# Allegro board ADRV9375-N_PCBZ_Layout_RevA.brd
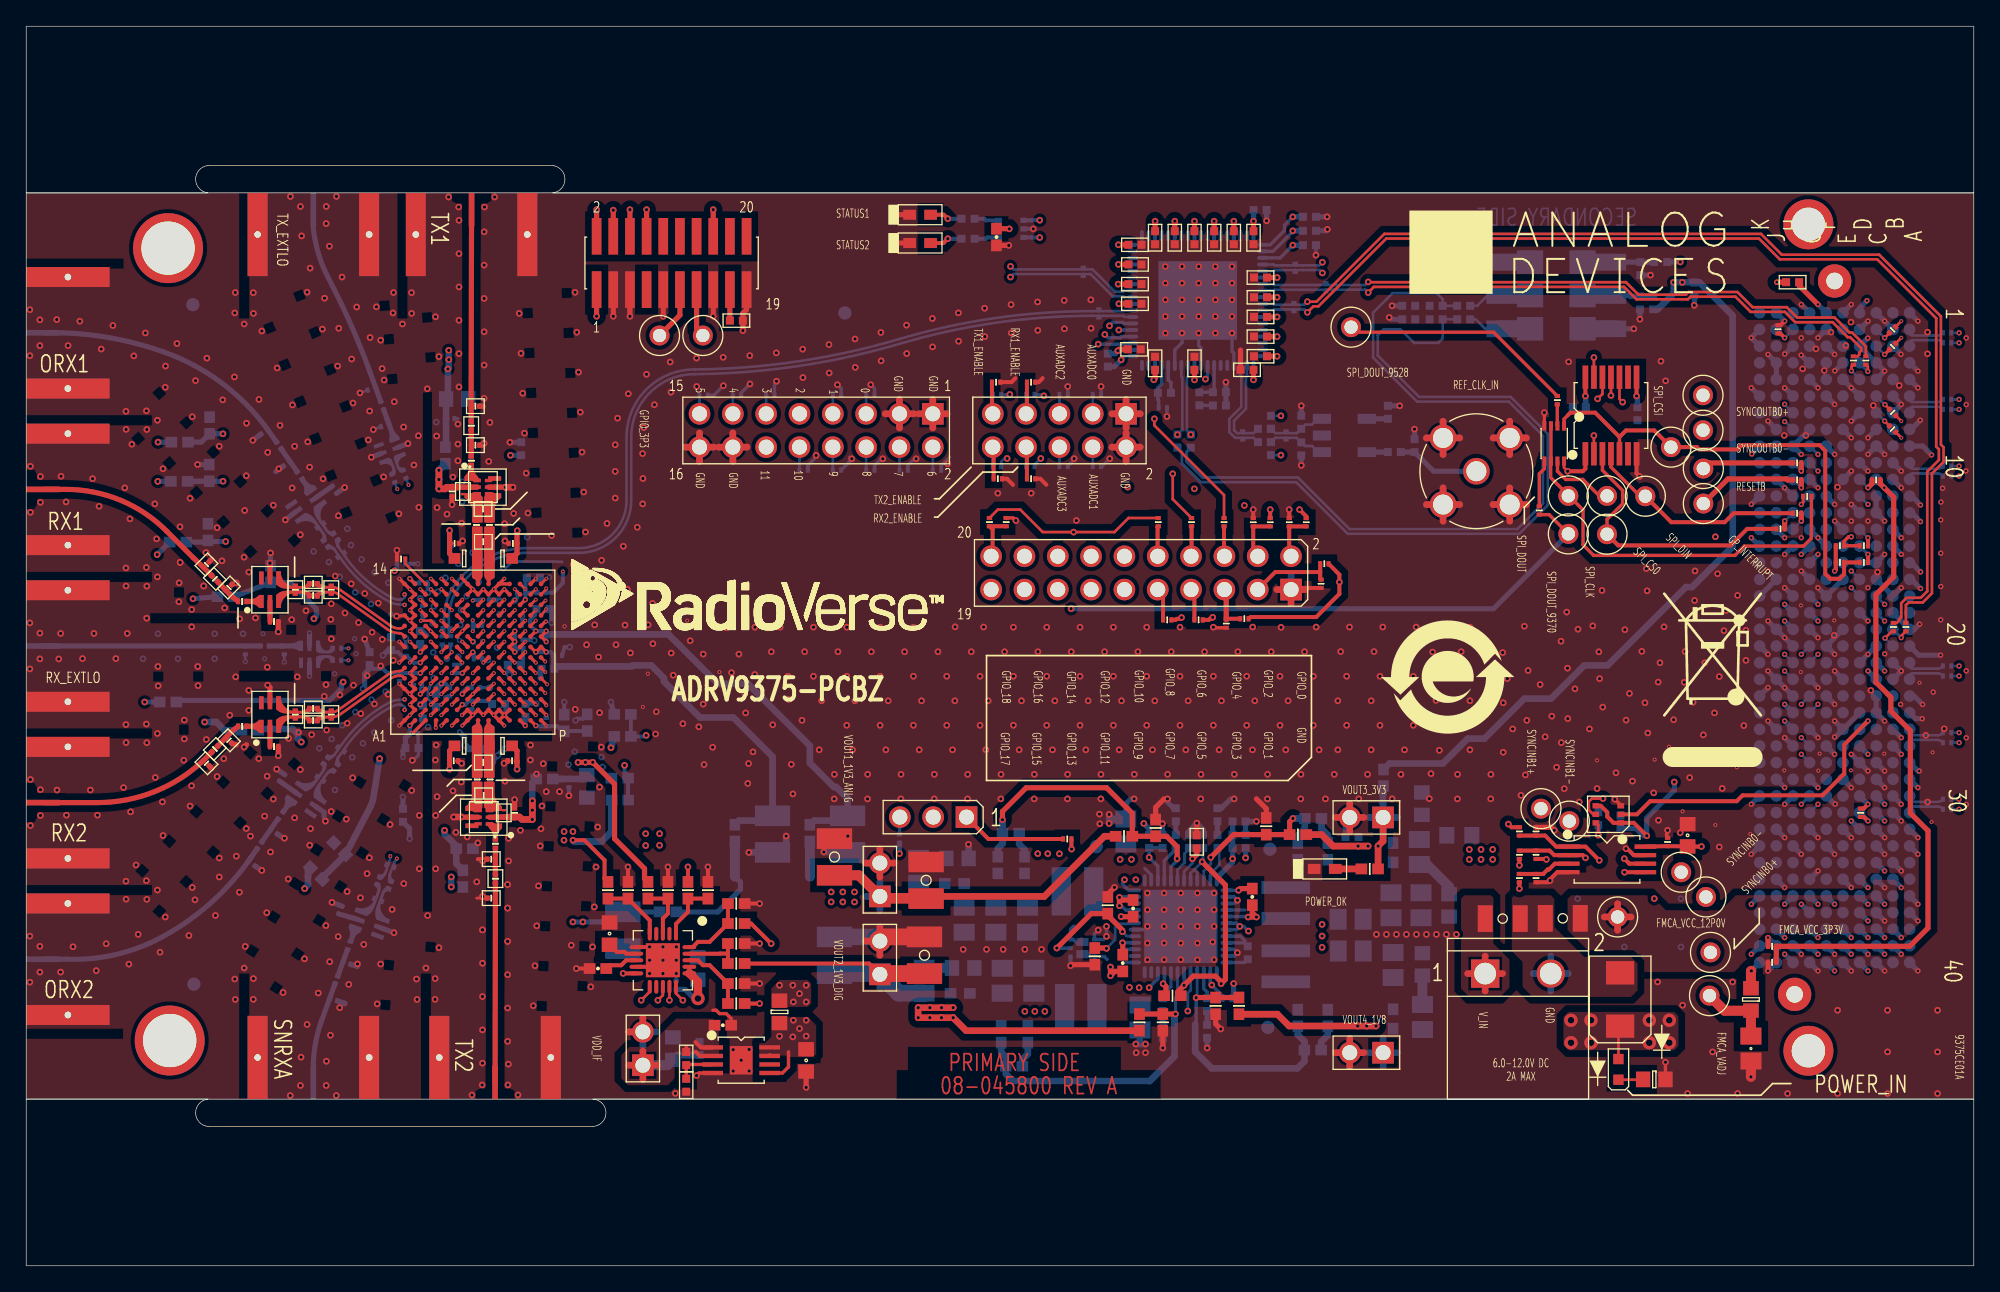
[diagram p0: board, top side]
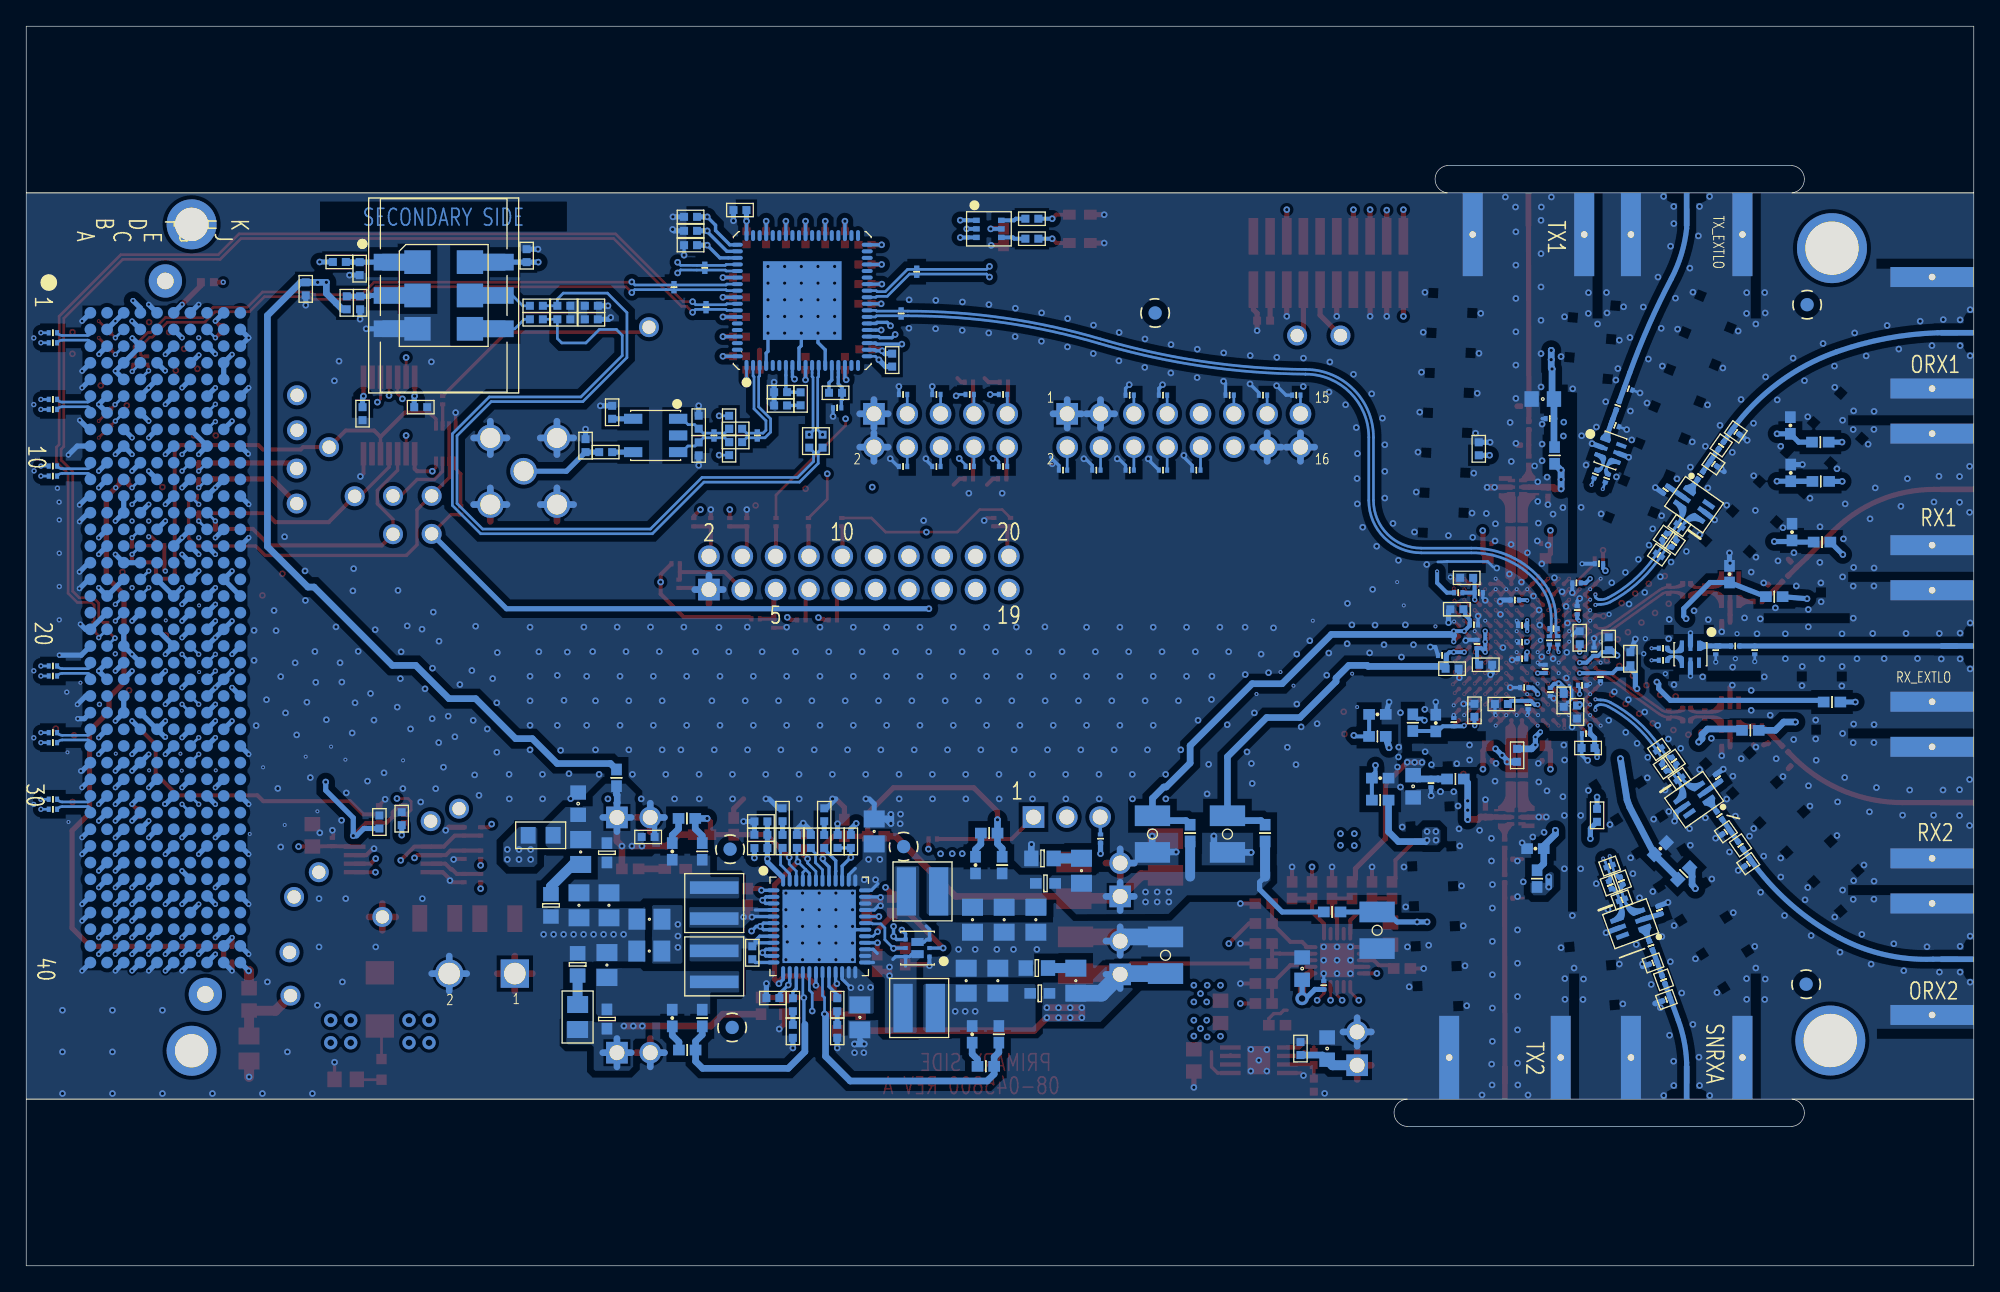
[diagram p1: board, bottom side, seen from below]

Outline 148.44 x 94.49 mm; copper layers: TOP, L2_GND, L3_PWR, L4_GND, L5_SIG, L6_GND, L7_SIG, L8_SIG, L9_GND, L10_SIG, L11_GND, L12_PWR, L13_GND, BOTTOM. Coordinates in mm from the lower left corner of the outline.
Outline path: 0,81.79 0,94.49 148.44,94.49 148.44,81.79 ; 0,81.79 0,12.7 ; 0,81.79 13.85,81.79 arc(12.91,82.83) 13.85,83.87 40.14,83.87 arc(41.06,82.83) 40.14,81.79 148.44,81.79 ; 0,81.79 148.44,81.79 ; 0,12.7 0,0 148.44,0 148.44,12.7 ; 0,12.7 148.44,12.7 ; 0,12.7 13.85,12.7 arc(12.91,11.66) 13.85,10.62 43.19,10.62 arc(44.19,11.66) 43.19,12.7 148.44,12.7 ; 148.44,12.7 148.44,81.79

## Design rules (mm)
net group DIFFPAIR0: nets SERDOUT0+ SERDOUT0-
net group DIFFPAIR1: nets SERDOUT1+ SERDOUT1-
net group DIFFPAIR2: nets SERDOUT3+ SERDOUT3-
net group DIFFPAIR3: nets SERDIN3+ SERDIN3-
net group DIFFPAIR4: nets SERDIN0+ SERDIN0-
net group DIFFPAIR5: nets SERDIN2+ SERDIN2-
net group DIFFPAIR13: nets SERDOUT2+ SERDOUT2-
net group DIFFPAIR15: nets SERDIN1+ SERDIN1-
net group DIFFPAIR16: nets TX_EXTLO+ TX_EXTLO-
net group DIFFPAIR17: nets ORX1+ ORX1-
net group DIFFPAIR18: nets RX1+ RX1-
net group DIFFPAIR19: nets RX2+ RX2-
net group DIFFPAIR20: nets ORX2+ ORX2-
net group DIFFPAIR22: nets RX_EXTLO+ RX_EXTLO-
net group DIFFPAIR24: nets DEV_CLK_IN+ DEV_CLK_IN-
net group DIFFPAIR26: nets GPIO_16 GPIO_17
net group DIFFPAIR27: nets GPIO_13 GPIO_14
net group DIFFPAIR28: nets GPIO_11 GPIO_12
net group DIFFPAIR29: nets GPIO_9 GPIO_10
net group DIFFPAIR30: nets GPIO_8 GPIO_15
net group DIFFPAIR36: nets SYNCOUTB0+ SYNCOUTB0-
net group DIFFPAIR37: nets SYNCINB0+ SYNCINB0-
net group DIFFPAIR38: nets SYNCINB1+ SYNCINB1-
net group DIFFPAIR56: nets SYSREF_IN+ SYSREF_IN-
net group DIFFPAIR59: nets CLK+ CLK-
net group DIFFPAIR61: nets UNNAMED_9_CAP_I337_N1 UNNAMED_9_CAP_I338_N1
net group DIFFPAIR62: nets SNRXA+ SNRXA-
net group DIFFPAIR63: nets FPGA_SYSREF+ FPGA_SYSREF-
net group DIFFPAIR64: nets UNNAMED_6_AD9370V2_I832_SERDI_3 UNNAMED_6_AD9370V2_I832_SERDIN2
net group DIFFPAIR65: nets UNNAMED_6_AD9370V2_I832_SERDI_1 UNNAMED_6_AD9370V2_I832_SERDIN0
net group DIFFPAIR66: nets UNNAMED_6_AD9370V2_I832_SERDI_4 UNNAMED_6_AD9370V2_I832_SERDIN3
net group DIFFPAIR67: nets UNNAMED_6_AD9370V2_I832_SERDI_2 UNNAMED_6_AD9370V2_I832_SERDIN1
net group DIFFPAIR68: nets UNNAMED_6_AD9370V2_I832_SERDO_1 UNNAMED_6_AD9370V2_I832_SERDOUT
net group DIFFPAIR69: nets UNNAMED_6_AD9370V2_I832_SERDO_4 UNNAMED_6_AD9370V2_I832_SERDO_5
net group DIFFPAIR70: nets UNNAMED_6_AD9370V2_I832_SERDO_2 UNNAMED_6_AD9370V2_I832_SERDO_3
net group DIFFPAIR71: nets UNNAMED_6_AD9370V2_I832_SERDO_6 UNNAMED_6_AD9370V2_I832_SERDO_7
net group DIFFPAIR72: nets VCXO_IN+ VCXO_IN-
net group DIFFPAIR73: nets UNNAMED_5_CAP_I916_N1 UNNAMED_5_RES_I897_N2
net group DIFFPAIR74: nets FPGA_REF_CLK+ FPGA_REF_CLK-
net group DIFFPAIR75: nets DIR_CLK+ DIR_CLK-
net group DIFFPAIR76: nets FPGA_AUX_CLK+ FPGA_AUX_CLK-
nets with their own width: min track width 0.254; nets AGND

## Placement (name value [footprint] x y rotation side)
C200  TBD0201  [C0201]  13.74 53.45 45 top
C201  18pF  [C0201]  14.37 52.37 315 top
C202  TBD0201  [C0201]  15.45 51.7 45 top
C203  TBD0201  [C0201]  18.89 49.1 0 top
C204  TBD0201  [C0201]  20.51 51.54 90 top
C205  18pF  [C0201]  21.88 51.08 0 top
C206  18pF  [C0201]  21.88 51.99 0 top
C207  TBD0201  [C0201]  23.25 51.54 90 top
C208  TBD0201  [C0201]  13.74 38.31 315 top
C209  18pF  [C0201]  14.37 39.39 45 top
C211  TBD0201  [C0201]  15.45 40.06 315 top
C212  TBD0201  [C0201]  18.89 39.58 0 top
C213  TBD0201  [C0201]  20.51 42.02 90 top
C214  18pF  [C0201]  21.88 41.56 0 top
C215  18pF  [C0201]  21.88 42.48 0 top
C216  TBD0201  [C0201]  23.25 42.02 90 top
C217  TBD0201  [C0201]  23.43 20.29 340 bottom
C218  18pF  [C0201]  23.64 21.8 70 bottom
C219  TBD0201  [C0201]  24.45 23.08 340 bottom
C220  TBD0201  [C0201]  23.95 27.12 70 bottom
C221  TBD0201  [C0201]  26.82 27.89 160 bottom
C222  18pF  [C0201]  27.71 29.02 70 bottom
C223  18pF  [C0201]  26.85 29.34 70 bottom
C224  TBD0201  [C0201]  27.75 30.47 160 bottom
C225  TBD0201  [C0201]  18.14 63.57 215 bottom
C226  18pF  [C0201]  19.25 62.53 305 bottom
C227  TBD0201  [C0201]  19.84 61.13 215 bottom
C228  TBD0201  [C0201]  23.49 59.16 305 bottom
C229  TBD0201  [C0201]  22.42 56.44 215 bottom
C230  18pF  [C0201]  23.58 55.57 305 bottom
C231  18pF  [C0201]  22.83 55.05 305 bottom
C232  TBD0201  [C0201]  23.99 54.19 215 bottom
C233  TBD0201  [C0201]  17.19 30.65 325 bottom
C234  18pF  [C0201]  17.78 32.05 55 bottom
C235  TBD0201  [C0201]  18.89 33.09 325 bottom
C236  18pF  [C0201]  19.5 37.19 235 bottom
C237  TBD0201  [C0201]  22.42 37.12 325 bottom
C238  18pF  [C0201]  22.83 38.5 55 bottom
C239  18pF  [C0201]  23.58 37.98 55 bottom
C240  TBD0201  [C0201]  23.99 39.36 325 bottom
C241  18pF  [C0201]  16.47 41.12 0 top
C242  18pF  [C0201]  24.6 24.41 70 bottom
C243  18pF  [C0201]  20.84 60.24 305 bottom
C244  18pF  [C0201]  19.38 34.33 55 bottom
C245  18pF  [C0201]  16.47 50.64 0 top
C301  18pF  [C0201]  33.92 64.04 90 top
C302  18pF  [C0201]  35.76 29.51 270 top
C303  TBD0201  [C0201]  34.81 57.69 0 top
C304  TBD0201  [C0201]  34.86 35.86 180 top
C305  18pF  [C0201]  33.92 61.37 90 top
C306  18pF  [C0201]  35.76 32.18 270 top
C307  TBD0201  [C0201]  32.65 55.06 0 top
C308  TBD0201  [C0201]  37.09 55.06 180 top
C309  TBD0201  [C0201]  34.32 56.48 90 top
C310  TBD0201  [C0201]  35.3 56.48 90 top
C311  TBD0201  [C0201]  34.84 55.19 0 top
C315  TBD0201  [C0201]  37.03 38.49 180 top
C316  TBD0201  [C0201]  32.58 38.49 0 top
C317  TBD0201  [C0201]  35.35 37.07 270 top
C318  TBD0201  [C0201]  34.37 37.07 270 top
C319  TBD0201  [C0201]  34.84 38.36 180 top
C320  10UF  [C0603]  32.85 66.07 0 bottom
C321  0.1uF  [C0201]  32.32 64.58 0 bottom
C322  0.1uF  [C0201]  32.46 59.02 270 top
C323  TBD0201  [C0201]  34.23 62.56 0 top
C324  TBD0201  [C0201]  34.23 65.53 0 top
C325  10UF  [C0603]  42.73 36.55 270 bottom
C326  0.1uF  [C0201]  41.37 36.79 270 bottom
C327  0.1uF  [C0201]  37.22 34.53 90 top
C328  TBD0201  [C0201]  35.44 31 180 top
C329  TBD0201  [C0201]  35.44 28.03 180 top
C330  TBD0201  [C0201]  16.69 46.93 270 bottom
C331  TBD0201  [C0201]  19.67 46.93 270 bottom
C332  100pF  [C0201]  23.68 47.07 0 bottom
C333  100pF  [C0201]  23.68 46.15 0 bottom
C334  TBD0201  [C0201]  26.33 66.86 200 bottom
C335  TBD0201  [C0201]  27.34 64.07 200 bottom
C336  100pF  [C0201]  28.84 60.34 290 bottom
C337  100pF  [C0201]  27.98 60.03 290 bottom
C401  0.1UF  [C0402]  104.28 62.02 180 bottom
C402  0.1UF  [C0402]  94.37 63.8 180 bottom
C403  0.1UF  [C0402]  94.37 62.79 180 bottom
C404  0.33uF  [C0402]  123.02 76.01 270 bottom
C405  0.1UF  [C0402]  110.3 77 270 bottom
C406  0.1UF  [C0402]  105.37 73.18 0 bottom
C407  0.1UF  [C0402]  94.87 62.29 270 bottom
C408  0.1UF  [C0402]  88.76 62.86 90 bottom
C409  0.1UF  [C0402]  94.87 64.3 90 bottom
C410  180pF  [C0402]  90.94 66.59 180 bottom
C411  1uF  [C0402]  90.94 65.58 180 bottom
C412  1000pF  [C0402]  86.76 66.55 0 bottom
C413  0.47uF  [C0201]  86.63 65.4 0 bottom
C414  0.1UF  [C0402#2]  73.95 78.42 90 top
C415  0.1UF  [C0402]  121.52 33.83 270 bottom
C416  0.1UF  [C0402]  119.82 34.08 270 bottom
C417  0.1UF  [C0402]  122.81 64.96 90 bottom
C418  0.1UF  [C0402]  118.37 65.45 0 bottom
C419  0.1UF  [C0402#2]  53.1 18.33 180 top
C420  1uF  [C0402]  94.04 80.48 0 bottom
C421  0.1UF  [C0402]  84.51 77.83 180 top
C422  0.1UF  [C0402]  84.51 76.33 180 top
C423  0.1UF  [C0402]  84.51 74.83 180 top
C424  0.1UF  [C0402]  84.51 73.33 180 top
C425  0.1UF  [C0402]  84.45 69.86 180 top
C426  0.1UF  [C0402]  86.04 68.79 270 top
C427  0.1UF  [C0402]  89.04 68.79 270 top
C428  0.1UF  [C0402]  93.04 68.3 0 top
C429  0.1UF  [C0402]  94.08 69.33 0 top
C430  0.1UF  [C0402]  94.08 70.83 0 top
C431  0.1UF  [C0402]  94.08 72.33 0 top
C432  0.1UF  [C0402]  94.08 73.83 0 top
C433  0.1UF  [C0402]  94.08 75.33 0 top
C434  0.1UF  [C0402]  93.54 78.36 90 top
C435  0.1UF  [C0402]  92.04 78.36 90 top
C436  0.1UF  [C0402]  90.54 78.36 90 top
C437  0.1UF  [C0402]  89.04 78.36 90 top
C438  0.1UF  [C0402]  87.54 78.36 90 top
C439  0.1UF  [C0402]  86.04 78.36 90 top
C501  0.1uF  [C0201]  31.71 47.67 270 bottom
C502  0.1uF  [C0201]  32.34 47.67 270 bottom
C503  0.1uF  [C0201]  79.07 60.93 0 bottom
C504  0.1uF  [C0201]  79.07 66.42 0 bottom
C505  0.1uF  [C0201]  81.61 60.93 0 bottom
C506  0.1uF  [C0201]  81.61 66.42 0 bottom
C507  0.1uF  [C0201]  146.41 39.88 0 bottom
C508  0.1uF  [C0201]  146.41 40.64 0 bottom
C509  0.1uF  [C0201]  142.25 70.07 45 top
C510  0.1uF  [C0201]  142.25 71.34 45 top
C511  0.1uF  [C0201]  146.41 34.8 0 bottom
C512  0.1uF  [C0201]  146.41 35.56 0 bottom
C513  0.1uF  [C0201]  146.41 44.96 0 bottom
C514  0.1uF  [C0201]  146.41 45.72 0 bottom
C515  0.1uF  [C0201]  146.41 70.36 0 bottom
C516  0.1uF  [C0201]  146.41 71.12 0 bottom
C517  0.1uF  [C0201]  146.41 65.28 0 bottom
C518  0.1uF  [C0201]  146.41 66.04 0 bottom
C519  0.1uF  [C0201]  142.25 63.78 315 top
C520  0.1uF  [C0201]  142.25 65.05 315 top
C521  0.1uF  [C0201]  146.41 60.2 0 bottom
C522  0.1uF  [C0201]  146.41 60.96 0 bottom
C523  0.1uF  [C0201]  64.33 66.37 0 bottom
C524  0.1uF  [C0201]  61.79 66.37 0 bottom
C525  0.1uF  [C0201]  56.71 66.37 0 bottom
C526  0.1uF  [C0201]  54.17 66.37 0 bottom
C527  0.1uF  [C0201]  51.63 66.37 0 bottom
C528  0.1uF  [C0201]  69.41 60.65 0 bottom
C529  0.1uF  [C0201]  66.87 60.65 0 bottom
C530  0.1uF  [C0201]  64.33 60.65 0 bottom
C531  0.1uF  [C0201]  61.79 60.65 0 bottom
C532  0.1uF  [C0201]  59.25 60.65 0 bottom
C601  100UF  [C1210]  68.59 29.38 90 top
C602  100UF  [C1210]  61.6 31.16 90 top
C603  1uF  [C0402]  29.4 39.47 0 bottom
C604  1uF  [C0402]  31.25 43.1 270 bottom
C605  0.1uF  [C0201]  29.55 40.56 0 bottom
C606  0.1uF  [C0201]  32.27 43.73 270 bottom
C608  100UF  [C1210]  45.48 25.57 270 bottom
C609  1uF  [C0402]  36 42.82 0 bottom
C610  0.1uF  [C0201]  33.97 42.74 270 bottom
C611  100UF  [C1210]  56.88 32.91 270 bottom
C612  1uF  [C0402]  39.76 45.51 180 bottom
C613  0.1uF  [C0201]  40.52 46.53 0 bottom
C614  1uF  [C0402#2]  33.41 31.8 0 bottom
C615  0.1uF  [C0201]  34.26 44.07 0 bottom
C616  1uF  [C0402#2]  41 41.37 90 bottom
C617  0.1uF  [C0201]  39.63 41.44 90 bottom
C618  1uF  [C0402#2]  45.45 42.03 180 bottom
C619  0.1uF  [C0201]  32.66 45.5 90 bottom
C620  1uF  [C0402]  26.17 46.27 90 bottom
C621  0.1uF  [C0201]  28.46 44.88 270 bottom
C622  1uF  [C0402#2]  45.24 37.17 180 bottom
C623  0.1uF  [C0201]  34.43 47.54 0 bottom
C624  1uF  [C0402]  27.82 47.42 90 bottom
C625  0.1uF  [C0201]  28.94 46.81 90 bottom
C626  1uF  [C0402#2]  18.62 52.72 90 bottom
C627  0.1uF  [C0201]  34.43 46.27 0 bottom
C628  1uF  [C0402#2]  23.89 31.8 135 bottom
C629  0.1uF  [C0201]  29.85 44.24 180 bottom
C630  1uF  [C0402#2]  13.95 60.44 90 bottom
C631  0.1uF  [C0201]  34.43 48.81 0 bottom
C632  1uF  [C0402#2]  13.85 55.93 90 bottom
C633  0.1uF  [C0201]  28.56 53.51 0 bottom
C634  1uF  [C0402#2]  13.98 64.05 90 bottom
C635  0.1uF  [C0201]  34.98 50.75 0 bottom
C636  1uF  [C0402]  37.2 45.82 180 bottom
C637  0.1uF  [C0201]  37.86 47.4 90 bottom
C638  100UF  [C1210]  68.46 23.67 90 top
C639  100UF  [C1210]  61.6 23.67 90 bottom
C640  0.1uF  [C0201]  30.22 49.98 90 bottom
C641  0.1uF  [C0201]  30.28 52.05 0 bottom
C642  0.01UF  [C0201]  37.73 51.31 180 bottom
C643  1uF  [C0402]  38.65 52.44 0 bottom
C644  1uF  [C0402]  38.06 42.34 90 bottom
C645  1uF  [C0402]  30.03 47.88 90 bottom
C646  1uF  [C0402]  30.24 42.21 270 bottom
C647  1uF  [C0402]  37.73 62.28 90 bottom
C648  10UF  [C0603]  51.19 22.65 90 bottom
C649  0.1uF  [C0201]  49.54 21.38 90 bottom
C650  10UF  [C0603]  44.46 25.32 90 top
C651  1uF  [C0402#2]  43.58 22.66 180 top
C652  100UF  [C1210]  62.6 32.91 270 bottom
C653  1uF  [C0402]  39.4 50.05 0 bottom
C654  0.1uF  [C0201]  38.1 48.86 180 bottom
C701  10uF  [C0805H60]  83.81 33.11 90 bottom
C702  1uF  [C0402]  89.7 32.35 270 bottom
C703  1uF  [C0402]  89.22 32.32 270 top
C704  2700PF  [C0402]  87.62 34.38 270 bottom
C705  10uF  [C0805H60]  84.9 18.94 270 bottom
C706  2700PF  [C0402]  86.63 17.87 90 bottom
C707  10uF  [C0805H60]  100.94 26.42 0 bottom
C708  3300pF  [C0402]  90.79 34.38 270 bottom
C709  10uF  [C0805H60]  100.95 23.99 0 bottom
C710  3300pF  [C0402]  90 17.87 90 bottom
C711  TBD0402  [C0402]  91.53 20.41 180 bottom
C712  TBD0402  [C0402]  92.44 33.87 180 bottom
C713  0.1UF  [C0402#2]  84.37 27.24 90 top
C714  0.01UF  [C0402#2]  76.09 30.54 270 bottom
C715  0.1UF  [C0402#2]  83.58 23.08 90 top
C716  0.01UF  [C0402#2]  76.34 17.64 90 bottom
C717  0.1UF  [C0402#2]  93.45 28.12 270 top
C718  0.01UF  [C0402#2]  99.2 31.58 270 bottom
C719  0.1UF  [C0402]  93.1 23.86 90 bottom
C720  0.01UF  [C0402#2]  99.2 18.88 90 bottom
C721  47uF  [C0805H60]  76.31 26.38 270 bottom
C722  47uF  [C0805H60]  73.9 26.38 270 bottom
C723  47uF  [C0805H60]  71.49 26.38 270 bottom
C724  47uF  [C0805H60]  68.01 30.11 90 bottom
C725  47uF  [C0805H60]  76.8 21.73 90 bottom
C726  47uF  [C0805H60]  74.38 21.73 90 bottom
C727  47uF  [C0805H60]  68.44 21.73 90 bottom
C728  47uF  [C0805H60]  104.02 27.48 270 bottom
C729  47uF  [C0805H60]  106.18 31.54 270 bottom
C730  47uF  [C0805H60]  104.18 22.92 90 bottom
C731  22UF  [C0805H53]  106.41 18.96 90 bottom
C732  47uF  [C0805H60]  131.45 16.56 270 top
C733  4.7uF  [C0603]  59.45 15.66 90 top
C734  4.7uF  [C0603]  49.29 16.56 270 bottom
C735  0.01UF  [C0402]  51.32 16.56 270 bottom
C736  10UF  [C0603]  106.37 35.23 90 bottom
C737  0.01UF  [C0402]  101.04 32.69 0 bottom
C738  0.1UF  [C0402]  127.14 74.47 90 bottom
C739  47uF  [C0805H60]  106.31 27.48 270 bottom
C801  0.01UF  [C0201]  143.27 48.69 90 top
C802  0.01UF  [C0201]  142.31 48.69 90 top
C803  0.1uF  [C0201]  125.1 32.3 270 top
C804  10UF  [C0603]  126.63 32.81 90 top
C805  0.01UF  [C0201]  140.22 69.01 270 top
C806  0.01UF  [C0201]  139.26 69.01 270 top
CR701  S2A-TP  [DO214AA3]  121.48 20.3 90 top
D401  LNJ314G8TRA (green)  [LED0603]  68.13 77.96 0 top
D402  LNJ314G8TRA (green)  [LED0603]  68.13 80.12 0 top
DS701  LNJ912W8CRA1 (blue)  [LED0603-2]  121.36 14.97 90 top
DS702  LNJ314G8TRA (green)  [LED0603]  98.97 30.25 0 top
E601  30OHM  [L0402]  54.01 32.98 90 bottom
E602  30OHM  [L0402]  33.28 29.51 90 bottom
E603  30OHM  [L0402]  42.76 41.4 270 bottom
E604  47OHM AT 100MHZ  [L0402]  45.45 40.35 0 bottom
E605  30OHM  [L0402]  17.03 40.81 0 bottom
E606  47OHM AT 100MHZ  [L0402]  45.24 35.5 0 bottom
E607  30OHM  [L0402]  10.8 42.97 0 bottom
E608  47OHM AT 100MHZ  [L0402]  15.21 51 0 bottom
E609  30OHM  [L0402]  22.11 29.89 315 bottom
E610  30OHM  [L0402]  11.66 59.79 0 bottom
E611  47OHM AT 100MHZ  [L0402]  11.57 55.16 0 bottom
E612  30OHM  [L0402]  11.69 62.78 0 bottom
E613  30OHM  [L0402]  59.73 32.98 90 bottom
E701  120OHM  [L0603]  70.75 29.15 180 bottom
E702  470OHM  [L0603]  71.18 20.76 180 bottom
E703  470OHM  [L0603]  104.18 31.48 90 bottom
E704  470OHM  [L0603]  104.18 18.81 270 bottom
E705  39OHM  [L0805]  109.23 32.81 0 bottom
E706  30OHM  [L0402]  103.45 37.19 90 bottom
F701  2A  [F1206]  117.11 26.48 180 top
F702  2A  [F1206]  112.53 26.46 0 top
J200  132255-11  [CNAMPHENOL132255-11]  0.76 59.18 180 top
J201  132255-11  [CNAMPHENOL132255-11]  0.76 35.31 180 top
J202  132255-11  [CNAMPHENOL132255-11]  21.88 13.46 270 bottom
J203  132255-11  [CNAMPHENOL132255-11]  0.76 71.12 180 bottom
J204  132255-11  [CNAMPHENOL132255-11]  0.76 23.37 180 bottom
J305  132255-11  [CNAMPHENOL132255-11]  33.94 81.03 90 top
J306  132255-11  [CNAMPHENOL132255-11]  35.73 13.46 270 top
J307  132255-11  [CNAMPHENOL132255-11]  0.76 47.24 180 bottom
J308  132255-11  [CNAMPHENOL132255-11]  21.88 81.03 90 bottom
J401  142-0701-201  [CNJOHNSON142-0701-201]  110.53 60.57 0 top
L200  TBD0201  [L0201]  13.74 53.45 225 top
L201  TBD0201  [L0201]  14.37 52.37 135 top
L202  TBD0201  [L0201]  15.45 51.7 225 top
L204  TBD0201  [L0201]  20.51 51.54 90 top
L205  TBD0201  [L0201]  21.88 51.08 180 top
L206  TBD0201  [L0201]  21.88 51.99 180 top
L207  TBD0201  [L0201]  23.25 51.54 90 top
L208  TBD0201  [L0201]  13.74 38.31 135 top
L209  TBD0201  [L0201]  14.37 39.39 225 top
L211  TBD0201  [L0201]  15.45 40.06 135 top
L213  TBD0201  [L0201]  20.51 42.02 90 top
L214  TBD0201  [L0201]  21.88 41.56 180 top
L215  TBD0201  [L0201]  21.88 42.48 180 top
L216  TBD0201  [L0201]  23.25 42.02 90 top
L217  TBD0201  [L0201]  23.43 20.29 160 bottom
L218  TBD0201  [L0201]  23.64 21.8 250 bottom
L219  TBD0201  [L0201]  24.45 23.08 160 bottom
L221  TBD0201  [L0201]  26.82 27.89 160 bottom
L222  TBD0201  [L0201]  27.71 29.02 250 bottom
L223  TBD0201  [L0201]  26.85 29.34 250 bottom
L224  TBD0201  [L0201]  27.75 30.47 160 bottom
L225  TBD0201  [L0201]  18.14 63.57 35 bottom
L226  TBD0201  [L0201]  19.25 62.53 125 bottom
L227  TBD0201  [L0201]  19.84 61.13 35 bottom
L229  TBD0201  [L0201]  22.42 56.44 35 bottom
L230  TBD0201  [L0201]  23.58 55.57 125 bottom
L231  TBD0201  [L0201]  22.83 55.05 125 bottom
L232  TBD0201  [L0201]  23.99 54.19 35 bottom
L233  TBD0201  [L0201]  17.19 30.65 145 bottom
L234  TBD0201  [L0201]  17.78 32.05 235 bottom
L235  TBD0201  [L0201]  18.89 33.09 145 bottom
L237  TBD0201  [L0201]  22.42 37.12 145 bottom
L238  TBD0201  [L0201]  22.83 38.5 235 bottom
L239  TBD0201  [L0201]  23.58 37.98 235 bottom
L240  TBD0201  [L0201]  23.99 39.36 145 bottom
L301  TBD0201  [L0201]  33.92 64.04 270 top
L302  TBD0201  [L0201]  35.76 29.51 90 top
L303  TBD0201  [L0201]  34.81 57.69 180 top
L304  TBD0201  [L0201]  34.86 35.86 0 top
L305  TBD0201  [L0201]  33.28 59.02 270 top
L306  TBD0201  [L0201]  36.39 34.53 90 top
L307  TBD0603  [L0603]  33.38 53.92 180 top
L308  TBD0603  [L0603]  36.3 53.92 180 top
L311  TBD0201  [L0201]  34.84 55.19 180 top
L315  TBD0603  [L0603]  36.3 39.63 0 top
L316  TBD0603  [L0603]  33.38 39.63 0 top
L319  TBD0201  [L0201]  34.84 38.36 0 top
L323  TBD0201  [L0201]  34.23 62.56 180 top
L324  TBD0201  [L0201]  34.23 65.53 180 top
L328  TBD0201  [L0201]  35.44 31 0 top
L329  TBD0201  [L0201]  35.44 28.03 0 top
L340  27NH  [L0402]  31.95 61.77 270 bottom
L341  27NH  [L0402]  39.51 37.11 180 bottom
L700  2.2uH  [LSMSQ157H83]  80.12 28.54 180 bottom
L701  2.2uH  [LSMSQ157H83]  80.38 19.65 180 bottom
L702  6.8uH  [LSMSQ157H122]  96 27.65 90 bottom
L703  6.8uH  [LSMSQ157H122]  96 22.82 270 bottom
NOREF  -  [unnamed]  135.84 79.39 0 top
NOREF#2  -  [#2]  -140.27 -270.64 0 top
NOREF#3  -  [#2]  65.26 103.22 0 top
NOREF#4  -  [#2]  154.73 149.81 0 top
NOREF#5  -  [#2]  -96.05 -6.87 0 top
NOREF#6  -  [#2]  -140.27 -270.64 0 top
NOREF#7  -  [#2]  0 81.79 0 top
NOREF#8  -  [#2]  250.38 231.5 0 top
NOREF#9  -  [#2]  100.91 127.05 0 top
NOREF#10  -  [#2]  43.34 10.64 0 top
NOREF#11  -  [#2]  148.44 81.79 0 top
NOREF#12  -  [unnamed]  135.84 16.39 0 top
NOREF#13  -  [#2]  148.44 12.7 0 top
NOREF#14  -  [#2]  148.44 12.7 90 top
NOREF#15  -  [#2]  137.8 54.91 0 top
NOREF#16  -  [unnamed]  10.81 77.57 0 top
NOREF#17  -  [#2]  108.34 44.88 0 top
NOREF#18  -  [#2]  0 0 90 top
NOREF#19  -  [#2]  0 0 90 top
NOREF#20  -  [unnamed]  10.93 17.17 0 top
NOREF#21  -  [#2]  -140.27 -270.64 0 top
NOREF#22  -  [#2]  277 2.84 0 top
NOREF#23  -  [unnamed]  12.7 73.26 0 bottom
NOREF#24  -  [unnamed]  94.79 31.76 0 bottom
NOREF#25  -  [unnamed]  12.78 21.46 0 bottom
NOREF#26  -  [unnamed]  81.56 31.95 0 bottom
NOREF#27  -  [#2]  105.42 74.09 180 bottom
NOREF#28  -  [unnamed]  62.4 72.63 90 bottom
NOREF#29  -  [unnamed]  94.63 18.17 0 bottom
P501  TSW-105-08-G-D  [CNSAMTEC2X5H338LD36]  83.83 64.94 180 top
P502  PEC10DAAN  [CNBERGF2X10H335LD32]  96.4 51.55 180 top
P503  TSW-108-08-G-D-ST  [CNSAMTECTSW-108-08-G-D-ST]  69.1 64.94 180 top
P504  FTSH-110-01-L-DV-K  [CNHDR2X10H251]  49.19 76.44 0 top
P701  Z5.530.3225.0  [CNWIELAND3225]  111.2 22.27 0 top
P702  SAMTECTSW10608GS3PIN  [CNBERG1X3H205LD36]  71.67 34.2 180 top
P703  TSW-102-08-G-S  [CNSAMTEC1X2H330LD36]  65.06 28.16 90 top
P704  TSW-102-08-G-S  [CNSAMTEC1X2H330LD36]  65.06 22.21 90 top
P705  TSW-102-08-G-S  [CNSAMTEC1X2H330LD36]  103.42 34.18 180 top
P706  TSW-102-08-G-S  [CNSAMTEC1X2H330LD36]  103.42 16.24 180 top
P707  TSW-102-08-G-S  [CNSAMTEC1X2H330LD36]  47 15.29 90 top
P801  ASP-134488-01  [CNSAMTECASP-134488-01]  143.55 72.64 270 bottom
Q701  SIA906EDJ-T1-GE3  [POWERPAKSC70-6]  80.51 24.22 90 bottom
R201  0  [R0201]  14.37 52.37 315 top
R202  0  [R0201]  16.47 50.64 0 top
R203  0  [R0201]  18.89 49.1 0 top
R204  0  [R0201]  16.47 41.12 0 top
R205  0  [R0201]  21.88 51.08 0 top
R206  0  [R0201]  21.88 51.99 0 top
R207  0  [R0201]  24.6 24.41 70 bottom
R208  0  [R0201]  20.84 60.24 305 bottom
R209  0  [R0201]  14.37 39.39 45 top
R210  0  [R0201]  19.38 34.33 55 bottom
R212  0  [R0201]  18.89 39.58 0 top
R214  0  [R0201]  21.88 41.56 0 top
R215  0  [R0201]  21.88 42.48 0 top
R218  0  [R0201]  23.64 21.8 70 bottom
R220  0  [R0201]  23.95 27.12 70 bottom
R222  0  [R0201]  27.71 29.02 70 bottom
R223  0  [R0201]  26.85 29.34 70 bottom
R226  0  [R0201]  19.25 62.53 305 bottom
R228  0  [R0201]  23.49 59.16 305 bottom
R230  0  [R0201]  23.58 55.57 305 bottom
R231  0  [R0201]  22.83 55.05 305 bottom
R234  0  [R0201]  17.78 32.05 55 bottom
R236  0  [R0201]  19.5 37.19 55 bottom
R238  0  [R0201]  22.83 38.5 55 bottom
R239  0  [R0201]  23.58 37.98 55 bottom
R301  0  [R0201]  33.92 64.04 90 top
R302  0  [R0201]  35.76 29.51 270 top
R303  0  [R0201]  33.92 61.37 90 top
R304  0  [R0201]  35.76 32.18 270 top
R309  TBD0201  [R0201]  34.32 56.48 90 top
R310  TBD0201  [R0201]  35.3 56.48 90 top
R312  0  [R0201]  18.18 47.24 0 bottom
R313  0  [R0201]  27.13 65.57 290 bottom
R317  TBD0201  [R0201]  35.35 37.07 270 top
R318  TBD0201  [R0201]  34.37 37.07 270 top
R401  49.9  [R0402#2]  105.81 62.52 270 bottom
R402  0  [R0402#2]  103.78 65.06 270 bottom
R403  24.9  [R0402#2]  97.18 64.3 270 bottom
R404  24.9  [R0402#2]  97.18 62.27 270 bottom
R405  100  [R0201]  96.02 63.29 270 bottom
R406  100  [R0201]  92.72 63.29 270 bottom
R407  0  [R0402#2]  124.57 76.52 180 bottom
R408  0  [R0402#2]  124.01 73.41 270 bottom
R409  0  [R0402#2]  122.99 73.41 90 bottom
R410  0  [R0402#2]  109.56 72.15 180 bottom
R411  0  [R0402#2]  109.56 73.18 180 bottom
R412  49.9  [R0402#2]  107.46 72.15 0 bottom
R413  0  [R0402#2]  107.46 73.18 180 bottom
R414  0  [R0402#2]  87.74 62.86 90 bottom
R415  10.2K  [R0402#2]  89.42 66.09 90 bottom
R416  10K  [R0402#2]  82.44 69.04 270 bottom
R417  10K  [R0402#2]  97.8 77.8 180 bottom
R418  10K  [R0402#2]  97.8 79.96 0 bottom
R419  10K  [R0402#2]  97.8 78.89 0 bottom
R420  200  [R0402#2]  71.79 78.29 180 bottom
R421  200  [R0402#2]  71.79 79.82 180 bottom
R422  100  [R0201]  96.63 73.07 270 bottom
R423  100  [R0201]  96.72 76.08 90 bottom
R424  100  [R0201]  80.57 75.77 270 bottom
R425  100  [R0201]  81.75 72.59 90 bottom
R426  0  [R0201]  116.7 65.99 90 top
R427  0  [R0201]  115.33 57.58 270 top
R428  0  [R0402#2]  105.37 72.15 180 bottom
R429  100  [R0201]  99.07 74.6 270 bottom
R501  100  [R0201]  32.03 48.56 0 bottom
R502  10K  [R0201]  39.29 51.31 0 bottom
R503  10K  [R0201]  133.07 24.35 0 top
R504  1K  [R0201]  133.07 23.13 180 top
R505  14.3K  [R0201]  28.57 53.88 0 top
R506  10K  [R0201]  74.05 59.99 0 top
R507  10K  [R0201]  73.92 67.36 0 top
R508  10K  [R0201]  76.59 67.36 0 top
R509  10K  [R0201]  76.59 59.99 0 top
R510  10K  [R0201]  92.85 49.32 180 top
R511  10K  [R0201]  94.81 56.68 270 top
R512  10K  [R0201]  98.94 53.51 180 top
R513  10K  [R0201]  97.56 56.68 270 top
R514  10K  [R0201]  91.46 48.95 270 top
R515  10K  [R0201]  93.52 56.68 90 top
R516  10K  [R0201]  98.69 51.99 270 top
R517  10K  [R0201]  96.26 56.68 90 top
R518  10K  [R0201]  74.69 56.69 90 top
R519  0  [R0201]  86.97 49.23 0 top
R520  0  [R0201]  86.28 56.69 90 top
R521  0  [R0201]  73.42 56.69 90 top
R522  0  [R0201]  89.35 49.23 0 top
R523  0  [R0201]  88.82 56.69 90 top
R524  0  [R0201]  91.29 56.69 90 top
R525  51K  [R0402#2]  54.13 72.05 180 top
R601  0  [R0402]  48.9 26.97 180 bottom
R602  56K  [R0402]  54.12 19.99 0 top
R603  10K  [R0402]  54.12 21.51 0 top
R604  10K  [R0402]  54.12 23.04 180 top
R605  10K  [R0402]  54.12 24.56 180 top
R606  10K  [R0402]  54.12 26.09 180 top
R607  10K  [R0402]  54.12 27.61 180 top
R608  10K  [R0402]  50.43 28.63 270 top
R609  10K  [R0402]  51.96 28.63 270 top
R610  10K  [R0402]  47.39 28.63 270 top
R611  10K  [R0402]  48.91 28.63 270 top
R612  10K  [R0402]  44.34 28.63 270 top
R613  10K  [R0402]  45.86 28.63 270 top
R614  0  [R0402#2]  34.81 38.91 270 bottom
R615  0  [R0402#2]  28.71 34.34 270 bottom
R701  2K  [R0603]  124.09 14.21 180 top
R702  200  [R0201]  79.35 32.53 180 top
R703  100K  [R0402]  87.36 20.59 0 top
R704  10K  [R0402#2]  87.62 32.35 270 bottom
R705  43.2K  [R0402#2]  85.59 32.35 270 bottom
R706  100K  [R0402#2]  86.6 32.35 90 bottom
R707  10K  [R0402#2]  86.63 19.9 90 bottom
R708  20K  [R0402#2]  90.79 32.35 270 bottom
R709  56K  [R0402#2]  92.44 31.84 180 bottom
R710  14K  [R0402#2]  92.44 32.85 0 bottom
R711  20K  [R0402#2]  90 19.9 90 bottom
R712  0  [R0201]  66.56 32.56 270 bottom
R713  32.4K  [R0402#2]  88.63 32.35 90 bottom
R714  10K  [R0402]  86.08 33.37 90 top
R715  0  [R0402]  75.04 32.98 0 bottom
R716  6.34K  [R0402]  83.67 32.74 180 top
R717  10.7K  [R0402]  74.05 30.54 270 bottom
R718  47K  [R0402]  81.45 23.58 90 top
R719  47K  [R0402]  82.43 27.48 270 top
R720  10K  [R0402]  86.63 18.55 90 top
R721  0  [R0402]  75.3 15.2 0 bottom
R722  10K  [R0402]  74.31 17.64 90 bottom
R723  6.34K  [R0402]  84.85 18.55 270 top
R724  10K  [R0402]  94.51 33.5 270 top
R725  0  [R0402]  98.08 34.1 0 bottom
R726  37.4K  [R0402]  96.91 31.58 270 bottom
R727  31.6K  [R0402]  96.93 32.87 0 top
R728  10K  [R0402]  90.65 19.81 90 top
R729  0  [R0402]  98.06 16.45 0 bottom
R730  27.4K  [R0402]  96.91 18.88 90 bottom
R731  12.7K  [R0402]  92.43 19.81 270 top
R732  0.1  [R0603]  70.98 31.05 0 bottom
R733  0.1  [R0603]  71.41 22.69 0 bottom
R734  0.1  [R0603]  108.45 27.47 270 bottom
R735  200  [R0402]  102.4 30.25 180 top
R736  0  [R0603]  57.41 19.35 270 top
R737  0.47  [R0603]  106.41 22.97 90 bottom
R738  0  [R0603]  131.45 20.3 90 top
R739  20K  [R0402#2]  50.3 15.79 90 top
R740  4.99K  [R0402#2]  50.3 13.76 90 top
R801  0  [R0201]  133.52 71.39 270 top
R802  0  [R0201]  134.98 61.2 0 top
R803  0  [R0201]  134.98 59.91 0 top
R804  0  [R0201]  133.71 56.17 0 top
R805  0  [R0201]  134.98 57.37 0 top
R806  0  [R0201]  135.75 58.64 180 top
R807  1K  [R0402#2]  134.63 74.98 0 top
R808  10K  [R0201]  138.24 54.89 0 top
R809  10K  [R0201]  138.24 53.62 0 top
R810  0  [R0201]  141 59.91 180 top
R811  0  [R0201]  140.06 54.89 0 top
R812  0  [R0201]  140.06 53.62 0 top
R813  0  [R0201]  73.99 66.42 0 bottom
R814  0  [R0201]  76.53 66.42 0 bottom
R815  0  [R0201]  139.81 34.53 90 top
R816  0  [R0201]  73.99 60.93 0 bottom
R817  0  [R0201]  76.53 60.93 0 bottom
R818  20K  [R0201]  113.8 33.11 90 top
R819  20K  [R0201]  115.07 33.11 270 top
R820  20K  [R0201]  113.8 31.33 270 top
R821  20K  [R0201]  115.07 31.33 90 top
R822  20K  [R0201]  113.8 29.55 270 top
R823  20K  [R0201]  115.07 29.55 90 top
T200  2450BL15B200E  [XFMR2450BL15B050]  18.58 51.54 0 top
T201  2450BL15B200E  [XFMR2450BL15B050]  18.58 42.02 0 top
T202  2450BL15B200E  [XFMR2450BL15B050]  26.16 26.08 70 bottom
T203  2450BL15B200E  [XFMR2450BL15B050]  21.31 58.02 305 bottom
T204  2450BL15B200E  [XFMR2450BL15B050]  21.31 35.53 55 bottom
T305  2450BL15B200E  [XFMR2450BL15B050]  34.81 59.36 270 top
T306  2450BL15B200E  [XFMR2450BL15B050]  34.87 34.2 90 top
T307  HHM1595A1  [T0805_A]  21.59 46.61 0 bottom
T308  HHM1595A1  [T0805_A]  27.69 62.15 290 bottom
T309  2500BL14M050T  [T0603-6P]  34.81 59.36 270 top
T310  2500BL14M050T  [T0603-6P]  34.87 34.2 90 top
T401  MABA-007159-000000  [ETC1]  100.47 63.29 270 bottom
TP401  WHT  [CNKEY5001TP]  100.97 71.55 0 top
TP402  WHT  [CNKEY5001TP]  117.54 55.79 0 top
TP501  WHT  [CNKEY5001TP]  51.57 70.91 0 top
TP502  WHT  [CNKEY5001TP]  48.27 70.91 0 top
TP801  WHT  [CNKEY5001TP]  123.41 58.66 0 top
TP802  WHT  [CNKEY5001TP]  120.48 55.77 0 top
TP803  WHT  [CNKEY5001TP]  127.83 58.1 0 top
TP804  WHT  [CNKEY5001TP]  127.83 60.77 0 top
TP805  WHT  [CNKEY5001TP]  127.8 66.36 0 top
TP806  WHT  [CNKEY5001TP]  127.8 63.69 0 top
TP807  WHT  [CNKEY5001TP]  128.03 28.11 45 top
TP808  WHT  [CNKEY5001TP]  126.14 30 45 top
TP809  WHT  [CNKEY5001TP]  117.54 58.69 0 top
TP810  WHT  [CNKEY5001TP]  115.45 34.84 0 top
TP811  WHT  [CNKEY5001TP]  117.61 33.89 0 top
TP812  WHT  [CNKEY5001TP]  128.3 20.59 0 top
TP813  WHT  [CNKEY5001TP]  120.48 58.69 0 top
TP814  WHT  [CNKEY5001TP]  125.36 62.4 0 top
TP815  WHT  [CNKEY5001TP]  121.29 26.59 0 top
TP816  WHT  [CNKEY5001TP]  128.37 23.89 0 top
U101  AD9370  [BGA196]  34.04 46.78 0 top
U401  AD9528BCPZ  [QFN72_10X10_PAD5_3X5_3]  89.29 73.58 180 bottom
U402  NC7WZ16P6X  [SC70]  75.07 79.04 270 bottom
U403  NC7WV125K8X  [US8]  116.46 62.68 180 top
U404  ADG3301BKSZ  [SC70-6]  120.58 34.41 90 top
U405  ADG3304SRU-EP  [TSSOP14]  120.79 64.82 0 top
U601  AD7291BCPZ  [QFN20_4X4_PAD2_6X2_6]  48.52 23.29 180 top
U701  ADP5054ACPZ  [QFN48_7X7_PAD5_6X5_6]  88 25.87 270 bottom
U702  ADP125ARHZ-R7  [MSOP8_PAD2_16X1_73]  54.49 15.67 270 top
U801  M24C02-WDW6TP  [TSSOP8]  120.48 30.98 270 top
Y401  122.88MEGHZ  [YSML276W197H71]  116.62 73.96 270 bottom
Y402  122.88MEGHz  [YSML555W358H240]  116.62 73.96 270 bottom
Y403  122.88MEGHZ  [LCC4H210]  116.62 73.96 270 bottom

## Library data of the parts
C200 C202-C204 C207 C208 C211-C213 C216 C217 C219-C221 C224 C225 C227-C229 C232 C233 C235 C237 C240 C303 C304 C307-C311 C315-C319 C323 C324 C328-C331 C334 C335 = CAP: User Part Number: UPN; part number: CAP_SM-TBD0201,TBD0201,TBD0201,E005718,C0201
C201 C205 C206 C209 C214 C215 C218 C222 C223 C226 C230 C231 C234 C236 C238 C239 C241-C245 C301 C302 C305 C306 = CAP: Tolerance: 5; User Part Number: UPN; part number: CAP_SM-18PF,25V,5,E014429,C0201; tolerance: 5
C320 C325 C648 C650 C736 C804 = CAP: Tolerance: 20; User Part Number: UPN; part number: CAP_SM-10UF,6.3V,20,E007143,C0603; tolerance: 20
C321 C322 C326 C327 C501-C532 C605 C606 C610 C613 C615 C617 C619 C621 C623 C625 C627 C629 C631 C633 C635 C637 C640 C641 C649 C654 C803 = CAP: Tolerance: 10; User Part Number: UPN; part number: CAP_SM-0.1UF,6.3V,10,E011567,C0201; tolerance: 10
C332 C333 C336 C337 = CAP: Tolerance: 10; User Part Number: UPN; part number: CAP_SM-100PF,25V,10,E006763,C0201; tolerance: 10
C401-C403 C405-C409 C414-C419 C421-C439 C713 C715 C717 C719 C738 = CAP: Tolerance: 10; User Part Number: UPN; alternate symbols: C0402_ALT; part number: CAP_SM-0.1UF,16V,10,E007200,C0402; tolerance: 10
C404 = CAP: Tolerance: 10; User Part Number: UPN; alternate symbols: C0402_ALT; part number: CAP_SM-0.33UF,10V,10,E011273,C0402; tolerance: 10
C410 = CAP: Tolerance: 5; User Part Number: UPN; alternate symbols: C0402_ALT; part number: CAP_SM-180PF,50V,5,E012612,C0402; tolerance: 5
C411 C420 C603 C604 C609 C612 C614 C616 C618 C620 C622 C624 C626 C628 C630 C632 C634 C636 C643-C647 C651 C653 C702 C703 = CAP: Tolerance: 10; User Part Number: UPN; alternate symbols: C0402_ALT; part number: CAP_SM-1UF,6.3V,10,E007449,C0402; tolerance: 10
C412 = CAP: Tolerance: 5; User Part Number: UPN; alternate symbols: C0402_ALT; part number: CAP_SM-1000PF,50V,5,E012419,C0402; tolerance: 5
C413 = CAP: Tolerance: 20; User Part Number: UPN; part number: CAP_SM-0.47UF,4V,20,E008196,C0201; tolerance: 20
C601 C602 C608 C611 C638 C639 C652 = CAP: Tolerance: 20; User Part Number: UPN; part number: CAP_SM-100UF,6.3V,20,E006532,C1210; tolerance: 20
C642 C801 C802 C805 C806 = CAP: Tolerance: 10; User Part Number: UPN; part number: CAP_SM-0.01UF,10V,10,E007201,C0201; tolerance: 10
C701 C705 C707 C709 = CAP: Tolerance: 10; User Part Number: UPN; part number: CAP_SM-10UF,25V,10,E014704,C0805H60; tolerance: 10
C704 C706 = CAP: Tolerance: 10; User Part Number: UPN; alternate symbols: C0402_ALT; part number: CAP_SM-2700PF,50V,10,E006649,C0402; tolerance: 10
C708 C710 = CAP: Tolerance: 10; User Part Number: UPN; alternate symbols: C0402_ALT; part number: CAP_SM-3300PF,50V,10,E007461,C0402; tolerance: 10
C711 C712 = CAP: User Part Number: UPN; alternate symbols: C0402_ALT; part number: CAP_SM-TBD0402,TBD0402,TBD0402,E000381,C0402
C714 C716 C718 C720 C735 C737 = CAP: Tolerance: 10; User Part Number: UPN; alternate symbols: C0402_ALT; part number: CAP_SM-0.01UF,25V,10,E010983,C0402; tolerance: 10
C721-C730 C732 C739 = CAP: Tolerance: 20; User Part Number: UPN; part number: CAP_SM-47UF,6.3V,20,E008247,C0805H60; tolerance: 20
C731 = CAP: Tolerance: 20; User Part Number: UPN; part number: CAP_SM-22UF,6.3V,20,E006534,C0805H53; tolerance: 20
C733 C734 = CAP: Tolerance: 10; User Part Number: UPN; part number: CAP_SM-4.7UF,6.3V,10,E010382,C0603; tolerance: 10
CR701 = DIO: User Part Number: UPN; Tolerance: N/A; alternate symbols: (DO15_ALT); part number: DIO_SM-S2A-TP,50V,N/A,E006293,DO214AA3; tolerance: N/A
D401 D402 DS702 = DIOLED: Tolerance: N/A; User Part Number: UPN; part number: DIOLED_SM-LNJ314G8TRA (GREEN),4V,N/A,E006309,LED0603; tolerance: N/A
DS701 = DIOLED: Tolerance: N/A; User Part Number: UPN; part number: DIOLED_SM-LNJ912W8CRA1 (BLUE),2.9V,N/A,E014695,LED0603-2; tolerance: N/A
E601-E603 E605 E607 E609 E610 E612 E613 E706 = FERRITE: Tolerance: 25; User Part Number: UPN; alternate symbols: (L1210H59_ALT); part number: FERRITE_SM-30OHM,25,E015998,L0402; tolerance: 25
E604 E606 E608 E611 = FERRITE: Tolerance: 25; User Part Number: UPN; alternate symbols: (L1210H59_ALT); part number: FERRITE_SM-47OHM AT 100MHZ,25,E021634,L0402; tolerance: 25
E701 = FERRITE: Tolerance: 25; User Part Number: UPN; alternate symbols: (L1210H59_ALT); part number: FERRITE_SM-120OHM,25,E012242,L0603; tolerance: 25
E702-E704 = FERRITE: Tolerance: 25; User Part Number: UPN; alternate symbols: (L1210H59_ALT); part number: FERRITE_SM-470OHM,25,E021228,L0603; tolerance: 25
E705 = FERRITE: Tolerance: N/A; User Part Number: UPN; alternate symbols: (L1210H59_ALT); part number: FERRITE_SM-39OHM,N/A,E002359,L0805; tolerance: N/A
F701 F702 = FSFUSE: User Part Number: UPN; part number: FSFUSE_SM-2A,63V,E005321,F1206
J200-J204 J305-J308 = CNBNC5P: User Part Number: UPN; alternate symbols: (CNAMPHENOL132255-11_ALT); part number: CNBNC5P_SM-132255-11,E017863,CNAMPHENOL132255-11
J401 = CNBNC5P: User Part Number: UPN; alternate symbols: (CNAMPHENOL132255-11_ALT); part number: CNBNC5P_TH-142-0701-201,E000916,CNJOHNSON142-0701-201
L200-L202 L204-L209 L211 L213-L219 L221-L227 L229-L235 L237-L240 L301-L306 L311 L319 L323 L324 L328 L329 = IND: User Part Number: UPN; part number: IND_SM-TBD0201,TBD0201,E007524,L0201
L307 L308 L315 L316 = IND: User Part Number: UPN; part number: IND_SM-TBD0603,TBD0603,E002419,L0603
L340 L341 = IND: Tolerance: 5; User Part Number: UPN; part number: IND_SM-27NH,5,E022012,L0402; tolerance: 5
L700 L701 = IND: User Part Number: UPN; Tolerance: 20; part number: IND_SM-2.2UH,20,E016651,LSMSQ157H83; tolerance: 20
L702 L703 = IND: User Part Number: UPN; Tolerance: 20; part number: IND_SM-6.8UH,20,E017909,LSMSQ157H122; tolerance: 20
P501 = CN10P: User Part Number: UPN; part number: CN10P_TH-TSW-105-08-G-D,E006587,CNSAMTEC2X5H338LD36
P502 = CN20P: User Part Number: UPN; part number: CN20P_TH-PTC10DAAN,E000765,CNBERGF2X10H335LD32
P503 = CN16P_ODD_EVEN: User Part Number: UPN; part number: CN16P_ODD_EVEN_TH-TSW-108-08-G-D-ST,E007547,CNSAMTECTSW-108-08-G-D-ST
P504 = CN20P_V2: User Part Number: UPN; part number: CN20P_V2_SM-FTSH-110-01-L-DV-K,E020976,CNHDR2X10H251
P701 = CN2P: User Part Number: UPN; part number: CN2P_TH-Z5.530.3225.0,E008161,CNWIELAND3225
P702 = CN3P: User Part Number: UPN; part number: CN3P_TH-SAMTECTSW10608GS3PIN,E000812,CNBERG1X3H205LD36
P703-P707 = CN2P: User Part Number: UPN; part number: CN2P_TH-TSW-102-08-G-S,E006296,CNSAMTEC1X2H330LD36
P801 = CN400P_A_K: User Part Number: UPN; part number: CN400P_A_K_SM-ASP-134488-01,E011384,CNSAMTECASP-134488-01
Q701 = TRANNMOSFET_2PAD: User Part Number: UPN; part number: TRANNMOSFET_2PAD_SM-SIA906EDJ-T1-GE3,E015819,POWERPAKSC70-6
R201-R210 R212 R214 R215 R218 R220 R222 R223 R226 R228 R230 R231 R234 R236 R238 R239 R301-R304 R312 R313 R426 R427 R519-R524 R712 R801-R806 R810-R817 = RES: Tolerance: 5; User Part Number: UPN; part number: RES_SM-0,E004015,1/20W,5,R0201; tolerance: 5
R309 R310 R317 R318 = RES: User Part Number: UPN; part number: RES_SM-TBD0201,E004055,TBD0201,TBD0201,R0201
R401 R412 = RES: Tolerance: 1; User Part Number: UPN; alternate symbols: R0402_ALT; part number: RES_SM-49.9,E003750,1/16W,1,R0402; tolerance: 1
R402 R407-R411 R413 R414 R428 R601 R614 R615 = RES: Tolerance: 5; User Part Number: UPN; alternate symbols: R0402_ALT; part number: RES_SM-0,E003438,1/16W,5,R0402; tolerance: 5
R403 R404 = RES: Tolerance: 1; User Part Number: UPN; alternate symbols: R0402_ALT; part number: RES_SM-24.9,E003773,1/16W,1,R0402; tolerance: 1
R405 R406 = RES: Tolerance: 1; User Part Number: UPN; alternate symbols: R0402_ALT; part number: RES_SM-100,E007239,1/20W,1,R0201; tolerance: 1
R415 = RES: Tolerance: 1; User Part Number: UPN; alternate symbols: R0402_ALT; part number: RES_SM-10.2K,E019451,1/16W,1,R0402; tolerance: 1
R416-R419 R704 R707 = RES: Tolerance: 1; User Part Number: UPN; alternate symbols: R0402_ALT; part number: RES_SM-10K,E003751,1/16W,1,R0402; tolerance: 1
R420 R421 = RES: Tolerance: 1; User Part Number: UPN; alternate symbols: R0402_ALT; part number: RES_SM-200,E003753,1/16W,1,R0402; tolerance: 1
R422-R425 R429 R501 = RES: Tolerance: 1; User Part Number: UPN; part number: RES_SM-100,E007239,1/20W,1,R0201; tolerance: 1
R502 R503 R506-R518 R808 R809 = RES: Tolerance: 1; User Part Number: UPN; part number: RES_SM-10K,E004011,1/20W,1,R0201; tolerance: 1
R504 = RES: Tolerance: 1; User Part Number: UPN; part number: RES_SM-1K,E004010,1/20W,1,R0201; tolerance: 1
R505 = RES: Tolerance: 1; User Part Number: UPN; part number: RES_SM-14.3K,E014068,1/20W,1,R0201; tolerance: 1
R525 = RES: Tolerance: 1; User Part Number: UPN; alternate symbols: R0402_ALT; part number: RES_SM-51K,E013080,1/10W,1,R0402; tolerance: 1
R602 R709 = RES: Tolerance: 1; User Part Number: UPN; alternate symbols: R0402_ALT; part number: RES_SM-56K,E017978,1/10W,1,R0402; tolerance: 1
R603-R613 R714 R720 R722 R724 R728 = RES: Tolerance: 1; User Part Number: UPN; part number: RES_SM-10K,E003751,1/16W,1,R0402; tolerance: 1
R701 = RES: Tolerance: 1; User Part Number: UPN; part number: RES_SM-2K,E017866,1/16W,1,R0603; tolerance: 1
R702 = RES: Tolerance: 1; User Part Number: UPN; part number: RES_SM-200,E004008,1/20W,1,R0201; tolerance: 1
R703 R706 = RES: Tolerance: 5; User Part Number: UPN; alternate symbols: R0402_ALT; part number: RES_SM-100K,E003464,1/10W,5,R0402; tolerance: 5
R705 = RES: Tolerance: 1; User Part Number: UPN; alternate symbols: R0402_ALT; part number: RES_SM-43.2K,E018504,1/10W,1,R0402; tolerance: 1
R708 R711 R739 = RES: Tolerance: 1; User Part Number: UPN; alternate symbols: R0402_ALT; part number: RES_SM-20K,E003791,1/16W,1,R0402; tolerance: 1
R710 = RES: Tolerance: 1; User Part Number: UPN; alternate symbols: R0402_ALT; part number: RES_SM-14K,E019660,1/16W,1,R0402; tolerance: 1
R713 = RES: Tolerance: 1; User Part Number: UPN; alternate symbols: R0402_ALT; part number: RES_SM-32.4K,E017609,1/10W,1,R0402; tolerance: 1
R715 R721 R725 R729 = RES: Tolerance: 5; User Part Number: UPN; part number: RES_SM-0,E003438,1/16W,5,R0402; tolerance: 5
R716 R723 = RES: Tolerance: 1; User Part Number: UPN; part number: RES_SM-6.34K,E003777,1/16W,1,R0402; tolerance: 1
R717 = RES: Tolerance: 1; User Part Number: UPN; part number: RES_SM-10.7K,E019637,1/16W,1,R0402; tolerance: 1
R718 R719 = RES: Tolerance: 1; User Part Number: UPN; part number: RES_SM-47K,E008189,1/16W,1,R0402; tolerance: 1
R726 = RES: Tolerance: 1; User Part Number: UPN; part number: RES_SM-37.4K,E017173,1/10W,1,R0402; tolerance: 1
R727 = RES: Tolerance: 1; User Part Number: UPN; part number: RES_SM-31.6K,E019881,1/10W,1,R0402; tolerance: 1
R730 = RES: Tolerance: 1; User Part Number: UPN; part number: RES_SM-27.4K,E021819,1/10W,1,R0402; tolerance: 1
R731 = RES: Tolerance: 1; User Part Number: UPN; part number: RES_SM-12.7K,E019976,1/10W,1,R0402; tolerance: 1
R732-R734 = RES: Tolerance: 1; User Part Number: UPN; part number: RES_SM-0.1,E016658,1/10W,1,R0603; tolerance: 1
R735 = RES: Tolerance: 1; User Part Number: UPN; part number: RES_SM-200,E003753,1/16W,1,R0402; tolerance: 1
R736 R738 = RES: Tolerance: 5; User Part Number: UPN; part number: RES_SM-0,E006826,1/10W,5,R0603; tolerance: 5
R737 = RES: Tolerance: 5; User Part Number: UPN; part number: RES_SM-0.47,E015794,1/10W,5,R0603; tolerance: 5
R740 = RES: Tolerance: 1; User Part Number: UPN; alternate symbols: R0402_ALT; part number: RES_SM-4.99K,E006643,1/16W,1,R0402; tolerance: 1
R807 = RES: Tolerance: 5; User Part Number: UPN; alternate symbols: R0402_ALT; part number: RES_SM-1K,E020936,1/16W,5,R0402; tolerance: 5
R818-R823 = RES: Tolerance: 1; User Part Number: UPN; part number: RES_SM-20K,E004013,1/20W,1,R0201; tolerance: 1
T200-T204 T305 T306 = XFMR3600BL: User Part Number: UPN; alternate symbols: (XFMR2012); part number: XFMR3600BL_SM-2450BL15B200E,E011952,XFMR2450BL15B050
T307 T308 = XFMRBD0826: User Part Number: UPN; part number: XFMRBD0826_SM-HHM1595A1,E016462,T0805_A
T309 T310 = XFMR3600BL: User Part Number: UPN; alternate symbols: (XFMR2012); part number: XFMR3600BL_SM-2500BL14M050T,E011543,T0603-6P
T401 = XFMRETC1: User Part Number: UPN; part number: XFMRETC1_SM-MABA-007159-000000,E006308,ETC1
TP401 TP402 TP501 TP502 TP801-TP816 = CNTP1P: User Part Number: UPN; alternate symbols: (CNBANANA_ALT); part number: CNTP1P_TH-WHT,E005683,CNKEY5001TP
U101 = AD9370_V2: User Part Number: UPN; alternate symbols: (RDC-9501-14-0250); part number: AD9370_V2_SM-AD9370,E020941,BGA196
U401 = AD9528: User Part Number: UPN; part number: AD9528_SM-AD9528BCPZ,E019427,QFN72_10X10_PAD5_3X5_3
U402 = NC7WZ17P6X: User Part Number: UPN; part number: NC7WZ17P6X_SM-NC7WZ16P6X,E002060,SC70
U403 = CMOSNC7WV125K8X: User Part Number: UPN; part number: CMOSNC7WV125K8X_SM-NC7WV125K8X,E017378,US8
U404 = ADG3301: User Part Number: UPN; part number: ADG3301_SM-ADG3301BKSZ,E010847,SC70-6
U405 = ADG3304: User Part Number: UPN; part number: ADG3304_SM-ADG3304SRU-EP,E020776,TSSOP14
U601 = AD7291: User Part Number: UPN; part number: AD7291_SM-AD7291BCPZ,E017361,QFN20_4X4_PAD2_6X2_6
U701 = ADP5054: User Part Number: UPN; part number: ADP5054_SM-ADP5054ACPZ,E019222,QFN48_7X7_PAD5_6X5_6
U702 = ADP125: User Part Number: UPN; part number: ADP125_SM-ADP125ARHZ-R7,E012587,MSOP8_PAD2_16X1_73
U801 = ICM24CXX: User Part Number: UPN; part number: ICM24CXX_SM-M24C02-WDW6TP,E017713,TSSOP8
Y401 = XTALOSC6P: User Part Number: UPN; part number: XTALOSC6P_SM-122.88MEGHZ,E013348,YSML276W197H71
Y402 = XTALOSC6P_V2: User Part Number: UPN; part number: XTALOSC6P_V2_SM-122.88MEGHZ,E010834,YSML555W358H240
Y403 = XTALCPP: User Part Number: UPN; part number: XTALCPP_SM-122.88MEGHZ,E015639,LCC4H210

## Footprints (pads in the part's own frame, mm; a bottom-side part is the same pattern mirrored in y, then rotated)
BGA196
  round 0.356 smd: A1(-5.2,-5.2) A2(-5.2,-4.4) A3(-5.2,-3.6) A4(-5.2,-2.8) A5(-5.2,-2) A6(-5.2,-1.2) A7(-5.2,-0.4) A8(-5.2,0.4) A9(-5.2,1.2) A10(-5.2,2) A11(-5.2,2.8) A12(-5.2,3.6) A13(-5.2,4.4) A14(-5.2,5.2) B1(-4.4,-5.2) B2(-4.4,-4.4) B3(-4.4,-3.6) B4(-4.4,-2.8) B5(-4.4,-2) B6(-4.4,-1.2) B7(-4.4,-0.4) B8(-4.4,0.4) B9(-4.4,1.2) B10(-4.4,2) B11(-4.4,2.8) B12(-4.4,3.6) B13(-4.4,4.4) B14(-4.4,5.2) C1(-3.6,-5.2) C2(-3.6,-4.4) C3(-3.6,-3.6) C4(-3.6,-2.8) C5(-3.6,-2) C6(-3.6,-1.2) C7(-3.6,-0.4) C8(-3.6,0.4) C9(-3.6,1.2) C10(-3.6,2) C11(-3.6,2.8) C12(-3.6,3.6) C13(-3.6,4.4) C14(-3.6,5.2) D1(-2.8,-5.2) D2(-2.8,-4.4) D3(-2.8,-3.6) D4(-2.8,-2.8) D5(-2.8,-2) D6(-2.8,-1.2) D7(-2.8,-0.4) D8(-2.8,0.4) D9(-2.8,1.2) D10(-2.8,2) D11(-2.8,2.8) D12(-2.8,3.6) D13(-2.8,4.4) D14(-2.8,5.2) E1(-2,-5.2) E2(-2,-4.4) E3(-2,-3.6) E4(-2,-2.8) E5(-2,-2) E6(-2,-1.2) E7(-2,-0.4) E8(-2,0.4) E9(-2,1.2) E10(-2,2) E11(-2,2.8) E12(-2,3.6) E13(-2,4.4) E14(-2,5.2) F1(-1.2,-5.2) F2(-1.2,-4.4) F3(-1.2,-3.6) F4(-1.2,-2.8) F5(-1.2,-2) F6(-1.2,-1.2) F7(-1.2,-0.4) F8(-1.2,0.4) F9(-1.2,1.2) F10(-1.2,2) F11(-1.2,2.8) F12(-1.2,3.6) F13(-1.2,4.4) F14(-1.2,5.2) G1(-0.4,-5.2) G2(-0.4,-4.4) G3(-0.4,-3.6) G4(-0.4,-2.8) G5(-0.4,-2) G6(-0.4,-1.2) G7(-0.4,-0.4) G8(-0.4,0.4) G9(-0.4,1.2) G10(-0.4,2) G11(-0.4,2.8) G12(-0.4,3.6) G13(-0.4,4.4) G14(-0.4,5.2) H1(0.4,-5.2) H2(0.4,-4.4) H3(0.4,-3.6) H4(0.4,-2.8) H5(0.4,-2) H6(0.4,-1.2) H7(0.4,-0.4) H8(0.4,0.4) H9(0.4,1.2) H10(0.4,2) H11(0.4,2.8) H12(0.4,3.6) H13(0.4,4.4) H14(0.4,5.2) J1(1.2,-5.2) J2(1.2,-4.4) J3(1.2,-3.6) J4(1.2,-2.8) J5(1.2,-2) J6(1.2,-1.2) J7(1.2,-0.4) J8(1.2,0.4) J9(1.2,1.2) J10(1.2,2) J11(1.2,2.8) J12(1.2,3.6) J13(1.2,4.4) J14(1.2,5.2) K1(2,-5.2) K2(2,-4.4) K3(2,-3.6) K4(2,-2.8) K5(2,-2) K6(2,-1.2) K7(2,-0.4) K8(2,0.4) K9(2,1.2) K10(2,2) K11(2,2.8) K12(2,3.6) K13(2,4.4) K14(2,5.2) L1(2.8,-5.2) L2(2.8,-4.4) L3(2.8,-3.6) L4(2.8,-2.8) L5(2.8,-2) L6(2.8,-1.2) L7(2.8,-0.4) L8(2.8,0.4) L9(2.8,1.2) L10(2.8,2) L11(2.8,2.8) L12(2.8,3.6) L13(2.8,4.4) L14(2.8,5.2) M1(3.6,-5.2) M2(3.6,-4.4) M3(3.6,-3.6) M4(3.6,-2.8) M5(3.6,-2) M6(3.6,-1.2) M7(3.6,-0.4) M8(3.6,0.4) M9(3.6,1.2) M10(3.6,2) M11(3.6,2.8) M12(3.6,3.6) M13(3.6,4.4) M14(3.6,5.2) N1(4.4,-5.2) N2(4.4,-4.4) N3(4.4,-3.6) N4(4.4,-2.8) N5(4.4,-2) N6(4.4,-1.2) N7(4.4,-0.4) N8(4.4,0.4) N9(4.4,1.2) N10(4.4,2) N11(4.4,2.8) N12(4.4,3.6) N13(4.4,4.4) N14(4.4,5.2) P1(5.2,-5.2) P2(5.2,-4.4) P3(5.2,-3.6) P4(5.2,-2.8) P5(5.2,-2) P6(5.2,-1.2) P7(5.2,-0.4) P8(5.2,0.4) P9(5.2,1.2) P10(5.2,2) P11(5.2,2.8) P12(5.2,3.6) P13(5.2,4.4) P14(5.2,5.2)
C0201
  rect 0.305x0.406 smd: 1(-0.318,0) 2(0.318,0)
C0402
  rect 0.61x0.61 smd: 1(-0.495,0) 2(0.495,0)
C0402#2
  rect 0.889x0.813 smd: 1(-0.635,0) 2(0.635,0)
C0603
  rect 1.092x1.194 smd: 1(-0.851,0) 2(0.851,0)
C0805H53
  rect 1.295x1.6 smd: 1(-0.953,0) 2(0.953,0)
C0805H60
  rect 1.295x1.6 smd: 1(-0.953,0) 2(0.953,0)
C1210
  rect 1.575x2.692 smd: 1(-1.397,0) 2(1.397,0)
CNAMPHENOL132255-11
  rect 2.54x0.432 smd: 1(-0.508,0)
  rect 6.35x1.524 hole 0.508: 2(-2.413,4.25) 4(-2.413,-4.25)
  round 0.305 smd: 3(-2.413,4.25) 5(-2.413,-4.25)
CNBERG1X3H205LD36
  rect 1.651x1.651 hole 1.143: 1(0,0)
  round 1.651 hole 1.143: 2(2.54,0) 3(5.08,0)
CNBERGF2X10H335LD32
  rect 1.651x1.651 hole 1.143: 1(0,0)
  round 1.651 hole 1.143: 2(0,-2.54) 3(2.54,0) 4(2.54,-2.54) 5(5.08,0) 6(5.08,-2.54) 7(7.62,0) 8(7.62,-2.54) 9(10.16,0) 10(10.16,-2.54) 11(12.7,0) 12(12.7,-2.54) 13(15.24,0) 14(15.24,-2.54) 15(17.78,0) 16(17.78,-2.54) 17(20.32,0) 18(20.32,-2.54) 19(22.86,0) 20(22.86,-2.54)
CNHDR2X10H251
  rect 0.737x2.794 smd: 1(-5.715,-2.032) 2(-5.715,2.032) 3(-4.445,-2.032) 4(-4.445,2.032) 5(-3.175,-2.032) 6(-3.175,2.032) 7(-1.905,-2.032) 8(-1.905,2.032) 9(-0.635,-2.032) 10(-0.635,2.032) 11(0.635,-2.032) 12(0.635,2.032) 13(1.905,-2.032) 14(1.905,2.032) 15(3.175,-2.032) 16(3.175,2.032) 17(4.445,-2.032) 18(4.445,2.032) 19(5.715,-2.032) 20(5.715,2.032)
CNJOHNSON142-0701-201
  round 2.032 hole 1.524: 1(0,0) 2(-2.54,2.54) 3(2.54,2.54) 4(2.54,-2.54) 5(-2.54,-2.54)
CNKEY5001TP
  round 1.524 hole 1.016: 1(0,0)
CNSAMTEC1X2H330LD36
  rect 1.651x1.651 hole 1.143: 1(0,0)
  round 1.651 hole 1.143: 2(2.54,0)
CNSAMTEC2X5H338LD36
  rect 1.651x1.651 hole 1.143: 1(0,0)
  round 1.651 hole 1.143: 2(0,2.54) 3(2.54,0) 4(2.54,2.54) 5(5.08,0) 6(5.08,2.54) 7(7.62,0) 8(7.62,2.54) 9(10.16,0) 10(10.16,2.54)
CNSAMTECASP-134488-01
  round 2.54 hole 1.27 unplated: (-2.426,5.715) (51.956,8.763)
  round 0.889 smd: A1(0,0) A2(1.27,0) A3(2.54,0) A4(3.81,0) A5(5.08,0) A6(6.35,0) A7(7.62,0) A8(8.89,0) A9(10.16,0) A10(11.43,0) A11(12.7,0) A12(13.97,0) A13(15.24,0) A14(16.51,0) A15(17.78,0) A16(19.05,0) A17(20.32,0) A18(21.59,0) A19(22.86,0) A20(24.13,0) A21(25.4,0) A22(26.67,0) A23(27.94,0) A24(29.21,0) A25(30.48,0) A26(31.75,0) A27(33.02,0) A28(34.29,0) A29(35.56,0) A30(36.83,0) A31(38.1,0) A32(39.37,0) A33(40.64,0) A34(41.91,0) A35(43.18,0) A36(44.45,0) A37(45.72,0) A38(46.99,0) A39(48.26,0) A40(49.53,0) B1(0,1.27) B2(1.27,1.27) B3(2.54,1.27) B4(3.81,1.27) B5(5.08,1.27) B6(6.35,1.27) B7(7.62,1.27) B8(8.89,1.27) B9(10.16,1.27) B10(11.43,1.27) B11(12.7,1.27) B12(13.97,1.27) B13(15.24,1.27) B14(16.51,1.27) B15(17.78,1.27) B16(19.05,1.27) B17(20.32,1.27) B18(21.59,1.27) B19(22.86,1.27) B20(24.13,1.27) B21(25.4,1.27) B22(26.67,1.27) B23(27.94,1.27) B24(29.21,1.27) B25(30.48,1.27) B26(31.75,1.27) B27(33.02,1.27) B28(34.29,1.27) B29(35.56,1.27) B30(36.83,1.27) B31(38.1,1.27) B32(39.37,1.27) B33(40.64,1.27) B34(41.91,1.27) B35(43.18,1.27) B36(44.45,1.27) B37(45.72,1.27) B38(46.99,1.27) B39(48.26,1.27) B40(49.53,1.27) C1(0,2.54) C2(1.27,2.54) C3(2.54,2.54) C4(3.81,2.54) C5(5.08,2.54) C6(6.35,2.54) C7(7.62,2.54) C8(8.89,2.54) C9(10.16,2.54) C10(11.43,2.54) C11(12.7,2.54) C12(13.97,2.54) C13(15.24,2.54) C14(16.51,2.54) C15(17.78,2.54) C16(19.05,2.54) C17(20.32,2.54) C18(21.59,2.54) C19(22.86,2.54) C20(24.13,2.54) C21(25.4,2.54) C22(26.67,2.54) C23(27.94,2.54) C24(29.21,2.54) C25(30.48,2.54) C26(31.75,2.54) C27(33.02,2.54) C28(34.29,2.54) C29(35.56,2.54) C30(36.83,2.54) C31(38.1,2.54) C32(39.37,2.54) C33(40.64,2.54) C34(41.91,2.54) C35(43.18,2.54) C36(44.45,2.54) C37(45.72,2.54) C38(46.99,2.54) C39(48.26,2.54) C40(49.53,2.54) D1(0,3.81) D2(1.27,3.81) D3(2.54,3.81) D4(3.81,3.81) D5(5.08,3.81) D6(6.35,3.81) D7(7.62,3.81) D8(8.89,3.81) D9(10.16,3.81) D10(11.43,3.81) D11(12.7,3.81) D12(13.97,3.81) D13(15.24,3.81) D14(16.51,3.81) D15(17.78,3.81) D16(19.05,3.81) D17(20.32,3.81) D18(21.59,3.81) D19(22.86,3.81) D20(24.13,3.81) D21(25.4,3.81) D22(26.67,3.81) D23(27.94,3.81) D24(29.21,3.81) D25(30.48,3.81) D26(31.75,3.81) D27(33.02,3.81) D28(34.29,3.81) D29(35.56,3.81) D30(36.83,3.81) D31(38.1,3.81) D32(39.37,3.81) D33(40.64,3.81) D34(41.91,3.81) D35(43.18,3.81) D36(44.45,3.81) D37(45.72,3.81) D38(46.99,3.81) D39(48.26,3.81) D40(49.53,3.81) E1(0,5.08) E2(1.27,5.08) E3(2.54,5.08) E4(3.81,5.08) E5(5.08,5.08) E6(6.35,5.08) E7(7.62,5.08) E8(8.89,5.08) E9(10.16,5.08) E10(11.43,5.08) E11(12.7,5.08) E12(13.97,5.08) E13(15.24,5.08) E14(16.51,5.08) E15(17.78,5.08) E16(19.05,5.08) E17(20.32,5.08) E18(21.59,5.08) E19(22.86,5.08) E20(24.13,5.08) E21(25.4,5.08) E22(26.67,5.08) E23(27.94,5.08) E24(29.21,5.08) E25(30.48,5.08) E26(31.75,5.08) E27(33.02,5.08) E28(34.29,5.08) E29(35.56,5.08) E30(36.83,5.08) E31(38.1,5.08) E32(39.37,5.08) E33(40.64,5.08) E34(41.91,5.08) E35(43.18,5.08) E36(44.45,5.08) E37(45.72,5.08) E38(46.99,5.08) E39(48.26,5.08) E40(49.53,5.08) F1(0,6.35) F2(1.27,6.35) F3(2.54,6.35) F4(3.81,6.35) F5(5.08,6.35) F6(6.35,6.35) F7(7.62,6.35) F8(8.89,6.35) F9(10.16,6.35) F10(11.43,6.35) F11(12.7,6.35) F12(13.97,6.35) F13(15.24,6.35) F14(16.51,6.35) F15(17.78,6.35) F16(19.05,6.35) F17(20.32,6.35) F18(21.59,6.35) F19(22.86,6.35) F20(24.13,6.35) F21(25.4,6.35) F22(26.67,6.35) F23(27.94,6.35) F24(29.21,6.35) F25(30.48,6.35) F26(31.75,6.35) F27(33.02,6.35) F28(34.29,6.35) F29(35.56,6.35) F30(36.83,6.35) F31(38.1,6.35) F32(39.37,6.35) F33(40.64,6.35) F34(41.91,6.35) F35(43.18,6.35) F36(44.45,6.35) F37(45.72,6.35) F38(46.99,6.35) F39(48.26,6.35) F40(49.53,6.35) G1(0,7.62) G2(1.27,7.62) G3(2.54,7.62) G4(3.81,7.62) G5(5.08,7.62) G6(6.35,7.62) G7(7.62,7.62) G8(8.89,7.62) G9(10.16,7.62) G10(11.43,7.62) G11(12.7,7.62) G12(13.97,7.62) G13(15.24,7.62) G14(16.51,7.62) G15(17.78,7.62) G16(19.05,7.62) G17(20.32,7.62) G18(21.59,7.62) G19(22.86,7.62) G20(24.13,7.62) G21(25.4,7.62) G22(26.67,7.62) G23(27.94,7.62) G24(29.21,7.62) G25(30.48,7.62) G26(31.75,7.62) G27(33.02,7.62) G28(34.29,7.62) G29(35.56,7.62) G30(36.83,7.62) G31(38.1,7.62) G32(39.37,7.62) G33(40.64,7.62) G34(41.91,7.62) G35(43.18,7.62) G36(44.45,7.62) G37(45.72,7.62) G38(46.99,7.62) G39(48.26,7.62) G40(49.53,7.62) H1(0,8.89) H2(1.27,8.89) H3(2.54,8.89) H4(3.81,8.89) H5(5.08,8.89) H6(6.35,8.89) H7(7.62,8.89) H8(8.89,8.89) H9(10.16,8.89) H10(11.43,8.89) H11(12.7,8.89) H12(13.97,8.89) H13(15.24,8.89) H14(16.51,8.89) H15(17.78,8.89) H16(19.05,8.89) H17(20.32,8.89) H18(21.59,8.89) H19(22.86,8.89) H20(24.13,8.89) H21(25.4,8.89) H22(26.67,8.89) H23(27.94,8.89) H24(29.21,8.89) H25(30.48,8.89) H26(31.75,8.89) H27(33.02,8.89) H28(34.29,8.89) H29(35.56,8.89) H30(36.83,8.89) H31(38.1,8.89) H32(39.37,8.89) H33(40.64,8.89) H34(41.91,8.89) H35(43.18,8.89) H36(44.45,8.89) H37(45.72,8.89) H38(46.99,8.89) H39(48.26,8.89) H40(49.53,8.89) J1(0,10.16) J2(1.27,10.16) J3(2.54,10.16) J4(3.81,10.16) J5(5.08,10.16) J6(6.35,10.16) J7(7.62,10.16) J8(8.89,10.16) J9(10.16,10.16) J10(11.43,10.16) J11(12.7,10.16) J12(13.97,10.16) J13(15.24,10.16) J14(16.51,10.16) J15(17.78,10.16) J16(19.05,10.16) J17(20.32,10.16) J18(21.59,10.16) J19(22.86,10.16) J20(24.13,10.16) J21(25.4,10.16) J22(26.67,10.16) J23(27.94,10.16) J24(29.21,10.16) J25(30.48,10.16) J26(31.75,10.16) J27(33.02,10.16) J28(34.29,10.16) J29(35.56,10.16) J30(36.83,10.16) J31(38.1,10.16) J32(39.37,10.16) J33(40.64,10.16) J34(41.91,10.16) J35(43.18,10.16) J36(44.45,10.16) J37(45.72,10.16) J38(46.99,10.16) J39(48.26,10.16) J40(49.53,10.16) K1(0,11.43) K2(1.27,11.43) K3(2.54,11.43) K4(3.81,11.43) K5(5.08,11.43) K6(6.35,11.43) K7(7.62,11.43) K8(8.89,11.43) K9(10.16,11.43) K10(11.43,11.43) K11(12.7,11.43) K12(13.97,11.43) K13(15.24,11.43) K14(16.51,11.43) K15(17.78,11.43) K16(19.05,11.43) K17(20.32,11.43) K18(21.59,11.43) K19(22.86,11.43) K20(24.13,11.43) K21(25.4,11.43) K22(26.67,11.43) K23(27.94,11.43) K24(29.21,11.43) K25(30.48,11.43) K26(31.75,11.43) K27(33.02,11.43) K28(34.29,11.43) K29(35.56,11.43) K30(36.83,11.43) K31(38.1,11.43) K32(39.37,11.43) K33(40.64,11.43) K34(41.91,11.43) K35(43.18,11.43) K36(44.45,11.43) K37(45.72,11.43) K38(46.99,11.43) K39(48.26,11.43) K40(49.53,11.43)
